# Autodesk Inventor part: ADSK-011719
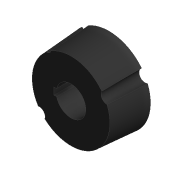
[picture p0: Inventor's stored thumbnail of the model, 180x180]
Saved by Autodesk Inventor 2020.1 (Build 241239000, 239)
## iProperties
Created: 1999-11
Part Number: ADSK-011719
Description: BUSHING,T/L,1.000B,2.75
Document SubType Name: Modeling
Designer: dmcquary
Material: Acier doux
Density: 7.86 g/cm^3
Appearance: Rubber-Black
Mass: 757.751 g
Surface Area: 168.518 cm^2
Volume: 96.406 cm^3
Control State: 0
Master: False
Checked Out: False
Shininess: 60.0
Length Units: 11269
Angle Units: 11279
Time Units: 11290
Mass Units: 11283
Length Display Precision: 3
Angle Display Precision: 2
Compacted: True
Dimensions: 70x32x70 mm
Mass: 0,758 kg
VLT_Material: Acier doux
Density: 0.0
Volumn: 0.0
Area: 0.0
PropertySet Name: Model Information
Author: dmcquary
Revision Number: -
Title: BUSHING,T/L,1.000B,2.75
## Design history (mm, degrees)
node "Solide1"
  node "Extrusion1" dims "d1" = 32, "d2" = -4 deg
  node "Extrusion2" dims "d8" = 25.4, "d9" = 0
  node "Hole1" dims "d15" = 10, "d16" = 9.525, "d17" = 6.35, "d18" = 60 deg, "d19" = 25.4, "d20" = 118 deg, "d34" = 6
  node "Hole2" dims "d23" = 6.6, "d24" = 9.525, "d25" = 6.35, "d26" = 60 deg, "d27" = 25.4, "d28" = 118 deg, "d35" = 16
  node "Extrusion3" dims "d32" = 25.4, "d33" = 0
sketch "Sketch1"
  geometry: C1 r 35 at (0, 0)
  constraints: 1 centre point
  dimensions: "d0" = 70 diameter of C1
sketch "Sketch2"
  geometry: L1 (0, 0)-(18.01, 0); L2 (9.5, 3)-(14.5, 3); L3 (14.5, 3)-(14.5, -3); L4 (14.5, -3)-(9.5, -3); L5 (9.5, -3)-(9.5, 3); C1 r 35 at (0, 0) reference; C2 r 12.5 at (0, 0); 1 further point
  constraints: 10 end point, 2 coincident, 2 horizontal, 2 parallel, 1 centre point, 1 midpoint, 1 perpendicular, 1 point on line
  dimensions: "d3" = 25 diameter of C2; "d4" = 5 distance of L3.end L4.end; "d7" = 14.5 distance from line of L3 C2.centre; "d36" = 6 distance of L2.end L3.end
sketch "Sketch3"
  geometry: L1 (-14.5, 3)-(-12.135, 3) reference; L2 (0, 0)-(-35, 0); L3 (0, 0)-(-26.812, -22.498); L4 (0, 0)-(30.311, 17.5); C1 r 32.762 at (0, 0) reference; A1 r 35 centre (0, 0) between (-35, 0) and (-26.812, -22.498); 2 further points
  constraints: 6 end point, 3 coincident, 3 point on circle, 1 centre point, 1 parallel
  dimensions: "d10" = 70 diameter of A1; "d12" = 40 deg angle of L3 L2; "d14" = 170 deg angle of L4 L3
sketch "Sketch4"
  geometry: L1 (-14.5, 3)-(-12.135, 3) reference; L2 (0, 0)-(-20.075, 28.67); L3 (0, 0)-(-28.935, 0); A1 r 12.5 centre (0, 0) between (-12.135, -3) and (-12.135, 3) reference; 1 further point
  constraints: 4 end point, 1 coincident, 1 parallel
  dimensions: "d21" = 35 distance of L2.start L2.end; "d22" = 55 deg angle of L3 L2
workaxis "Work Axis1"
node "Corps solides"
node "Corps surfaciques"
sketch "Sketch6"
  geometry: L1 (-7.805, -9.763)-(-6.505, -10.674); L2 (-6.505, -10.674)-(-19.42, -29.118); L3 (-19.42, -29.118)-(-20.72, -28.208); L4 (-20.72, -28.208)-(-7.805, -9.763); L5 (20.075, 28.67)-(0, 0); A1 r 12.5 centre (0, 0) between (12.135, 3) and (12.135, -3) reference; A2 r 3.3 centre (20.075, 28.67) between (17.286, 30.434) and (22.686, 26.652) reference; A3 r 35 centre (0, 0) between (29.744, -18.448) and (22.686, 26.652) reference; A4 r 35 centre (0, 0) between (-32.495, 13.002) and (23.332, -26.088) reference
  constraints: 10 end point, 2 parallel, 2 point on circle, 1 perpendicular
  dimensions: "d29" = 1.5875 distance of L2.end L3.end; "d30" = 0.79375 distance from line of L4 A1.centre; "d31" = 180 deg angle of L2 L5
